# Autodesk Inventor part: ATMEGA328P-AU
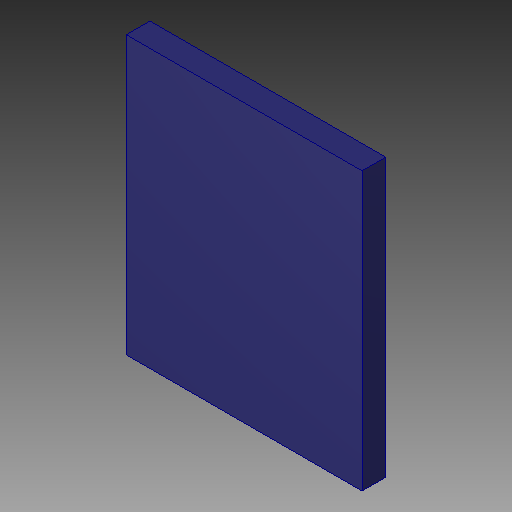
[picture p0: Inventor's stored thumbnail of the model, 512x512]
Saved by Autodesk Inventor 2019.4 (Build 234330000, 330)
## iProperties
Created: 2019-11
Part Number: ATMEGA328P-AU
Material: Generic
Document SubType Name: Modeling
Designer: Willist
Density: 1 g/cm^3
Appearance: QFP80P900X900X120-32N, ATMEGA328P-AU
Author: Willist
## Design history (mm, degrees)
sketch "QFP80P900X900X120-32N, ATMEGA328P-AU_1"
  geometry: L1 (-4.623, 5.309)-(5.334, 5.309); L2 (5.334, 5.309)-(5.334, -6.401); L3 (5.334, -6.401)-(-4.623, -6.401); L4 (-4.623, -6.401)-(-4.623, 5.309)
  constraints: 8 end point
extrude "Extrusion1" join sketch "QFP80P900X900X120-32N, ATMEGA328P-AU_1" distance "d0" = 1; taper "d1" = 0 deg
body "Solid1"
